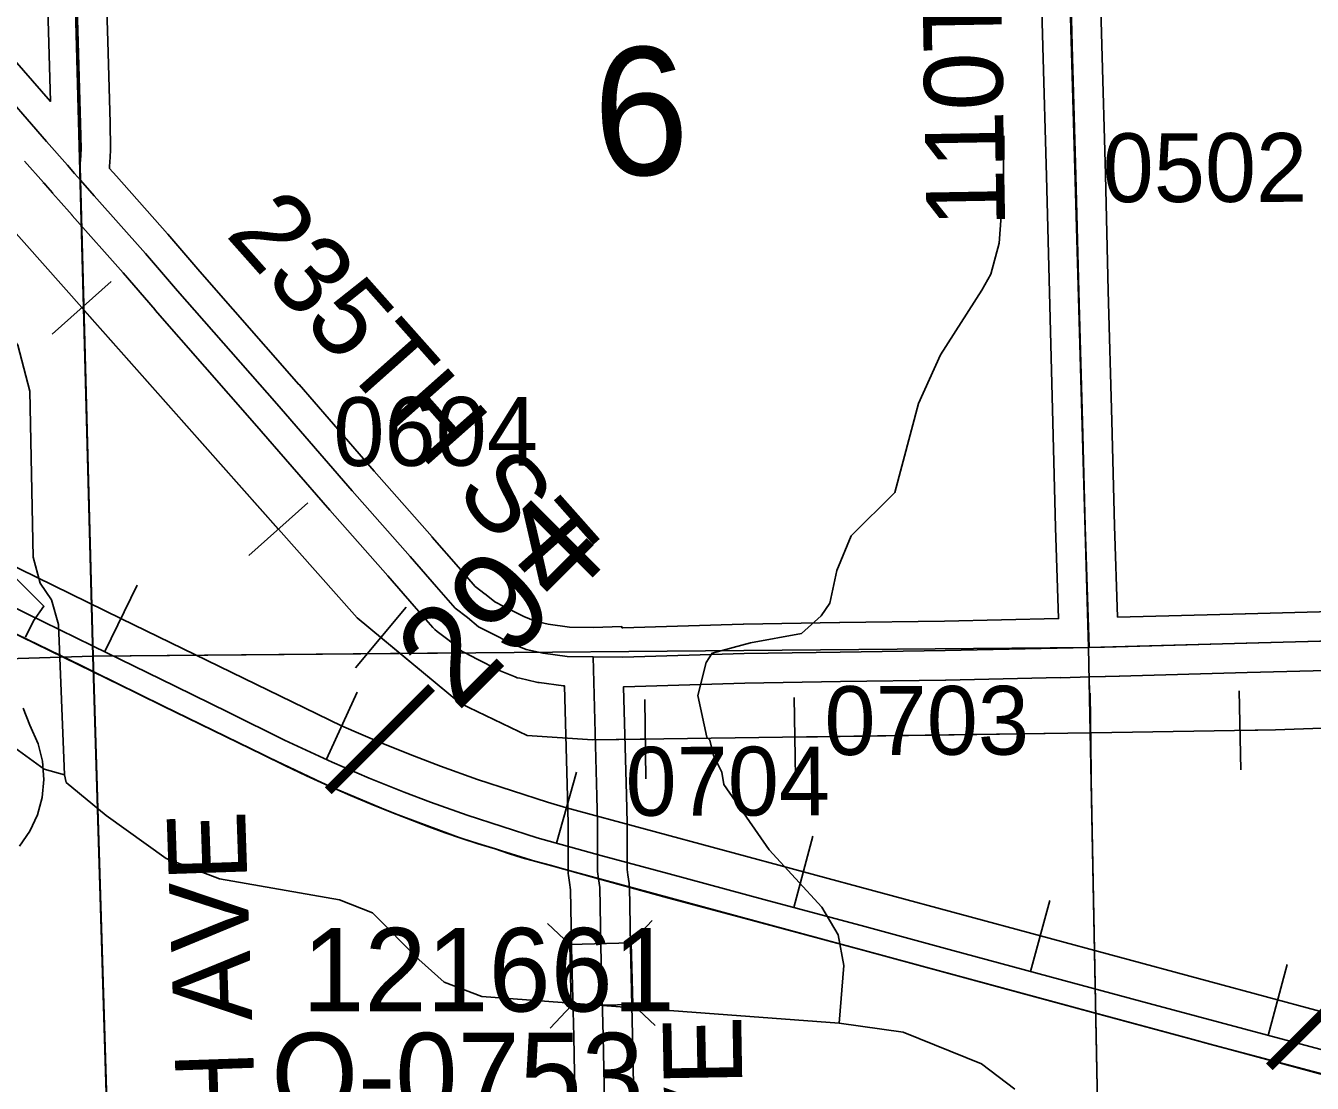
# Model space of a CAD drawing. Extents: x 128.7 to 185.5, y -21.4 to 12.6.
# Drawn here: x 134.119 to 135.429, y -9.118 to -8.042 of the extents above; entities that cross this region are included whole.
import ezdxf

# ---------------------------------------------------------------- set-up
doc = ezdxf.new("R2010")
doc.units = 0
for name, color, linetype in [('tdCoCoBndry', 7, 'Continuous'), ('tdCoCoBndryPart', 7, 'Continuous'), ('tdCoHydroRiver', 7, 'Continuous'), ('tdCoPipe', 7, 'Continuous'), ('tdCoPriCL', 7, 'Continuous'), ('tdCoPrimary', 7, 'Continuous'), ('tdCoPriNonDiv', 7, 'Continuous'), ('tdCoPriNonDivCL', 7, 'Continuous'), ('tdCoRRCL', 7, 'Continuous'), ('tdCoSecRdNmbr', 7, 'Continuous'), ('tdCoSecRdTxt', 7, 'Continuous'), ('tdCoSecRteBand', 7, 'Continuous'), ('tdCoSecRteCL', 7, 'Continuous'), ('tdCoSectLine', 7, 'Continuous'), ('tdCoSectLinePart', 7, 'Continuous'), ('tdCoSectNmbr', 7, 'Continuous'), ('tdCoShieldUsRte', 7, 'Continuous'), ('tdCoStrucSec', 7, 'Continuous'), ('tdCoStrucSecCoName', 7, 'Continuous'), ('tdCoStrucSecFHWANum', 7, 'Continuous'), ('tdCoSurfAsphalt', 7, 'Continuous'), ('tdCoSurfGravel', 7, 'Continuous'), ('tdCoTwpBndryShd', 7, 'Continuous'), ('tdStHwyPriRefPost1', 7, 'Continuous'), ('tdStHwyPriRefPost5', 7, 'Continuous')]:
    doc.layers.add(name, color=color, linetype=linetype)

msp = doc.modelspace()

# ---------------------------------------------------------------- linework, layer by layer
at = {"layer": 'tdCoCoBndry'}
for p, q in [((134.1615, -7.6994), (134.1879, -8.683)), ((134.1879, -8.683), (134.1615, -7.6994)), ((134.1879, -8.683), (134.219, -9.7062)), ((134.219, -9.7062), (134.1879, -8.683))]:
    msp.add_line(p, q, dxfattribs=at)
for points in [[(133.7886, 4.3475), (133.8188, 3.3421), (133.8473, 2.341), (133.878, 1.3376), (133.9067, 0.3357), (133.9391, -0.6703), (133.9673, -1.6731), (133.9961, -2.6778), (134.0303, -3.6816), (134.0608, -4.6883), (134.0947, -5.6895), (134.129, -6.6932), (134.1293, -6.7029), (134.1612, -7.6994), (134.1875, -8.683), (134.2186, -9.7062), (134.2417, -10.7094), (134.275, -11.7191), (134.2997, -12.7212), (134.329, -13.723)], [(133.8962, -2.6807), (134.0612, -7.7025), (134.1187, -9.7087), (134.1418, -10.7117), (134.1751, -11.7221), (134.2291, -13.7257), (134.2397, -13.7678), (134.2605, -13.7958), (134.2979, -13.818), (134.3318, -13.8228), (134.3294, -13.723), (134.3001, -12.7212), (134.2754, -11.7191), (134.2421, -10.7094), (134.219, -9.7062), (134.1879, -8.683), (134.1615, -7.6994), (134.1297, -6.7029)], [(140.1254, -13.5551), (139.3404, -13.58), (138.3387, -13.6015), (137.3418, -13.6288), (136.3432, -13.661), (135.3389, -13.6885), (134.3294, -13.723), (134.3001, -12.7212), (134.2754, -11.7191), (134.2421, -10.7094), (134.219, -9.7062), (134.1879, -8.683), (134.1615, -7.6994), (134.1297, -6.7029)]]:
    msp.add_lwpolyline(points, dxfattribs=at)
at = {"layer": 'tdCoCoBndryPart'}
msp.add_lwpolyline([(134.1758, -8.2449), (134.1875, -8.683), (134.2025, -9.1782)], dxfattribs=at)
at = {"layer": 'tdCoHydroRiver'}
for points in [[(135.1146, -8.1536), (135.1144, -8.2026), (135.1099, -8.2627), (135.1014, -8.2945), (135.0924, -8.3105), (135.0502, -8.3765), (135.028, -8.4261), (135.0038, -8.5167), (134.9594, -8.5606), (134.9446, -8.5958), (134.9377, -8.6291), (134.9287, -8.642), (134.9087, -8.66), (134.8569, -8.6694), (134.8177, -8.6801), (134.8117, -8.6897), (134.8032, -8.7231), (134.8124, -8.7654), (134.8156, -8.7685), (134.8193, -8.7842), (134.8277, -8.8013), (134.8296, -8.8138), (134.8758, -8.8803), (134.9296, -8.9387), (134.9462, -8.9666), (134.9518, -8.998), (134.9473, -9.0565)], [(134.1586, -8.8038), (134.1525, -8.6509), (134.1454, -8.6259), (134.1339, -8.6088), (134.1268, -8.5822), (134.1234, -8.4135), (134.1109, -8.3665), (134.1076, -8.3619), (134.1041, -8.3509), (134.0892, -8.3245), (134.0831, -8.3171)], [(134.0553, -8.7596), (134.1041, -8.7738), (134.1379, -8.7981), (134.1586, -8.8038), (134.1604, -8.8116), (134.2009, -8.8451), (134.2621, -8.8891), (134.3164, -8.9096), (134.4386, -8.9312), (134.4721, -8.9444), (134.5193, -8.9919), (134.5452, -9.0148), (134.5835, -9.0294), (134.9473, -9.0565), (135.0122, -9.0656), (135.0921, -9.098), (135.126, -9.1238)]]:
    msp.add_lwpolyline(points, dxfattribs=at)
at = {"layer": 'tdCoPipe'}
for p, q in [((134.146, -8.3554), (134.2062, -8.302)), ((134.3461, -8.5806), (134.4063, -8.527)), ((134.4548, -8.6951), (134.5062, -8.6331)), ((135.2037, -8.8016), (135.2026, -8.7209)), ((135.3559, -8.7989), (135.3545, -8.7184)), ((134.7505, -8.8079), (134.7493, -8.7273)), ((134.9026, -8.8058), (134.9014, -8.7253))]:
    msp.add_line(p, q, dxfattribs=at)
for points in [[(136.9009, -9.4255), (136.8169, -9.4094), (136.5505, -9.3406), (136.5159, -9.3231), (136.4089, -9.2225), (136.4044, -9.218), (135.9635, -8.7378), (135.3912, -8.758), (135.204, -8.7612), (134.6962, -8.7684), (134.6297, -8.7639), (134.5618, -8.7314), (134.4564, -8.6441), (134.037, -8.172)], [(134.3762, -8.5538), (134.1762, -8.3287)], [(134.7499, -8.7676), (134.6962, -8.7684), (134.6297, -8.7639), (134.5618, -8.7314), (134.4805, -8.6641)], [(135.2031, -8.7613), (134.902, -8.7655)], [(135.6562, -8.7486), (135.3912, -8.758), (135.3552, -8.7586)]]:
    msp.add_lwpolyline(points, dxfattribs=at)
at = {"layer": 'tdCoPriCL'}
msp.add_lwpolyline([(134.0884, -8.6507), (134.1751, -8.6926), (134.1883, -8.6991), (134.1994, -8.7045), (134.2023, -8.706), (134.205, -8.7073), (134.2584, -8.7336), (134.3608, -8.7836), (134.3828, -8.7945), (134.4049, -8.805), (134.4273, -8.8152), (134.4498, -8.8248), (134.4707, -8.8338), (134.4917, -8.8423), (134.5129, -8.8503), (134.5294, -8.8568), (134.5461, -8.8629), (134.5629, -8.8687), (134.5798, -8.8741), (134.5969, -8.8793), (134.6106, -8.8839), (134.6245, -8.8882), (134.6384, -8.8922), (134.6524, -8.8959), (134.702, -8.9096), (134.7724, -8.9291), (134.845, -8.9485), (134.9725, -8.9826), (135.13, -9.0254), (135.2167, -9.0488), (135.3035, -9.0723), (135.3283, -9.0791), (135.4689, -9.1164)], dxfattribs=at)
at = {"layer": 'tdCoPrimary'}
for points in [[(134.0884, -8.6505), (134.1754, -8.6926), (134.1883, -8.6989)], [(134.0884, -8.6505), (134.1754, -8.6926), (134.1883, -8.6989)], [(134.0884, -8.6505), (134.1754, -8.6926), (134.1883, -8.6989), (134.1883, -8.6989), (134.2588, -8.7336), (134.3612, -8.7836), (134.3832, -8.7945), (134.4053, -8.805), (134.4277, -8.8152), (134.4502, -8.8248), (134.471, -8.8338), (134.4921, -8.8423), (134.5133, -8.8503), (134.5298, -8.8568), (134.5465, -8.8629), (134.5633, -8.8687), (134.5802, -8.8741), (134.5972, -8.8793), (134.611, -8.8839), (134.6248, -8.8882), (134.6388, -8.8922), (134.6528, -8.8959), (134.7023, -8.9096), (134.7728, -8.9291), (134.8454, -8.9485), (134.9729, -8.9826), (135.1304, -9.0254), (135.3038, -9.0723), (135.3286, -9.0791), (135.4693, -9.1164)], [(134.1883, -8.6989), (134.1883, -8.6989), (134.2588, -8.7336), (134.3612, -8.7836), (134.3832, -8.7945), (134.4053, -8.805), (134.4277, -8.8152), (134.4502, -8.8248), (134.471, -8.8338), (134.4921, -8.8423), (134.5133, -8.8503), (134.5298, -8.8568), (134.5465, -8.8629), (134.5633, -8.8687), (134.5802, -8.8741), (134.5972, -8.8793), (134.611, -8.8839), (134.6248, -8.8882), (134.6388, -8.8922), (134.6528, -8.8959), (134.7023, -8.9096), (134.7728, -8.9291), (134.8454, -8.9485), (134.9729, -8.9826), (135.1304, -9.0254), (135.3038, -9.0723), (135.3286, -9.0791), (135.4693, -9.1164)], [(134.1883, -8.6989), (134.1883, -8.6989), (134.2588, -8.7336), (134.3612, -8.7836), (134.3832, -8.7945), (134.4053, -8.805), (134.4277, -8.8152), (134.4502, -8.8248), (134.471, -8.8338), (134.4921, -8.8423), (134.5133, -8.8503), (134.5298, -8.8568), (134.5465, -8.8629), (134.5633, -8.8687), (134.5802, -8.8741), (134.5972, -8.8793), (134.611, -8.8839), (134.6248, -8.8882), (134.6388, -8.8922), (134.6528, -8.8959), (134.7023, -8.9096), (134.7728, -8.9291), (134.8454, -8.9485), (134.9729, -8.9826), (135.1304, -9.0254), (135.3038, -9.0723), (135.3286, -9.0791), (135.4693, -9.1164)]]:
    msp.add_lwpolyline(points, dxfattribs=at)
at = {"layer": 'tdCoPriNonDiv'}
msp.add_lwpolyline([(134.0851, -8.6491), (134.3608, -8.7836), (134.4273, -8.8152), (134.4917, -8.8423), (134.5629, -8.8687), (134.6384, -8.8922), (135.3035, -9.0723), (136.2808, -9.3366)], dxfattribs=at)
at = {"layer": 'tdCoPriNonDivCL'}
for points in [[(134.0884, -8.6507), (134.1751, -8.6926)], [(134.0884, -8.6507), (134.1751, -8.6926), (134.1879, -8.6989)], [(134.1751, -8.6926), (134.1751, -8.6926), (134.188, -8.6989), (134.2584, -8.7336), (134.3608, -8.7836), (134.3828, -8.7945), (134.4049, -8.805), (134.4273, -8.8152), (134.4498, -8.8248), (134.4707, -8.8338), (134.4917, -8.8423), (134.5129, -8.8503), (134.5294, -8.8568), (134.5461, -8.8629), (134.5629, -8.8687), (134.5798, -8.8741), (134.5969, -8.8793), (134.6106, -8.8839), (134.6245, -8.8882), (134.6384, -8.8922), (134.6524, -8.8959), (134.702, -8.9096), (134.7724, -8.9291), (134.845, -8.9485), (134.9725, -8.9826), (135.13, -9.0254), (135.3035, -9.0723), (135.3283, -9.0791), (135.4689, -9.1164)], [(134.1879, -8.6989), (134.188, -8.6989), (134.2584, -8.7336), (134.3608, -8.7836), (134.3828, -8.7945), (134.4049, -8.805), (134.4273, -8.8152), (134.4498, -8.8248), (134.4707, -8.8338), (134.4917, -8.8423), (134.5129, -8.8503), (134.5294, -8.8568), (134.5461, -8.8629), (134.5629, -8.8687), (134.5798, -8.8741), (134.5969, -8.8793), (134.6106, -8.8839), (134.6245, -8.8882), (134.6384, -8.8922), (134.6524, -8.8959), (134.702, -8.9096), (134.7724, -8.9291), (134.845, -8.9485), (134.9725, -8.9826), (135.13, -9.0254), (135.3035, -9.0723), (135.3283, -9.0791), (135.4689, -9.1164)]]:
    msp.add_lwpolyline(points, dxfattribs=at)
at = {"layer": 'tdCoRRCL'}
for p, q in [((134.1996, -8.6783), (134.2326, -8.611)), ((134.4251, -8.7879), (134.4564, -8.7197)), ((134.6594, -8.8735), (134.6796, -8.8013)), ((134.9009, -8.9388), (134.9203, -8.8664)), ((135.142, -9.0041), (135.1615, -8.9316)), ((135.3839, -9.0693), (135.4033, -8.9968))]:
    msp.add_line(p, q, dxfattribs=at)
for points in [[(133.992, -8.5352), (134.2166, -8.645), (134.4406, -8.754), (134.4603, -8.7626), (134.4791, -8.7707), (134.4969, -8.7778), (134.5147, -8.7849), (134.5414, -8.7951), (134.5789, -8.8085), (134.6146, -8.82), (134.6502, -8.8316), (134.6697, -8.8374), (134.911, -8.9025), (135.152, -8.9678), (135.3934, -9.0327), (135.6349, -9.098)], [(135.481, -9.095), (135.3832, -9.0688), (135.2626, -9.0366), (135.1848, -9.0154), (135.0629, -8.9826), (134.9732, -8.9582), (134.8705, -8.9307), (134.774, -8.9047), (134.7045, -8.8861), (134.6398, -8.868), (134.5685, -8.845), (134.531, -8.8316), (134.5042, -8.8214), (134.4686, -8.8072), (134.4311, -8.791), (134.3826, -8.7687), (134.3257, -8.7406), (134.2712, -8.7136), (134.1872, -8.6725), (134.1205, -8.64), (134.0458, -8.6033), (133.9755, -8.5689)]]:
    msp.add_lwpolyline(points, dxfattribs=at)
at = {"layer": 'tdCoSecRteBand'}
for points in [[(134.1078, -8.0766), (134.1443, -8.1185), (134.1425, -8.0592), (134.1425, -8.0592), (134.1425, -8.0592), (134.1391, -7.9418), (134.1366, -7.8595), (134.1342, -7.7804), (134.132, -7.715), (134.13, -7.6516), (134.13, -7.6516), (134.13, -7.6516), (134.127, -7.5542), (134.1233, -7.4488), (134.1233, -7.4487), (134.1233, -7.4487), (134.1213, -7.3859), (134.1194, -7.3324), (134.1193, -7.3321), (134.1193, -7.3318), (134.1186, -7.2875)], [(134.7268, -8.6542), (134.8494, -8.6505), (134.8497, -8.6505), (134.8499, -8.6505), (134.9475, -8.649), (134.9476, -8.649), (134.9476, -8.649), (135.0545, -8.6475), (135.1705, -8.6449), (135.1675, -8.5523), (135.1675, -8.5522), (135.1675, -8.5521), (135.1648, -8.4453), (135.1611, -8.3132), (135.1611, -8.3131), (135.1611, -8.3131), (135.1582, -8.1948), (135.1545, -8.0629), (135.1545, -8.0628), (135.1545, -8.0628), (135.1508, -7.9265)], [(135.2107, -7.9248), (135.2144, -8.0612), (135.2181, -8.1931), (135.2181, -8.1932), (135.2181, -8.1932), (135.2211, -8.3115), (135.2248, -8.4437), (135.2248, -8.4437), (135.2248, -8.4437), (135.2275, -8.5504), (135.2305, -8.6435)], [(134.1991, -7.94), (134.2025, -8.0574), (134.205, -8.1405), (134.205, -8.1407), (134.205, -8.1408), (134.2055, -8.1662), (134.2055, -8.1674), (134.2054, -8.1686), (134.2047, -8.1809), (134.2047, -8.1811), (134.2047, -8.1813), (134.2045, -8.1833), (134.2043, -8.1867), (134.2043, -8.1867), (134.2114, -8.1948), (134.2634, -8.2534), (134.2636, -8.2536), (134.2638, -8.2538), (134.2962, -8.2917), (134.3972, -8.4067), (134.3972, -8.4068), (134.3973, -8.4068), (134.4739, -8.495), (134.5328, -8.5618), (134.5328, -8.5618), (134.5329, -8.5619), (134.5597, -8.5927), (134.5767, -8.6121), (134.5869, -8.6199), (134.5874, -8.6203), (134.5878, -8.6206), (134.5966, -8.6279), (134.6057, -8.6325), (134.6261, -8.6428), (134.6378, -8.6476), (134.651, -8.6507), (134.6725, -8.6535), (134.6966, -8.6538), (134.726, -8.653), (134.726, -8.6542), (134.7268, -8.6542)], [(134.6799, -9.2199), (134.6769, -9.0703), (134.6746, -8.98), (134.6746, -8.9798), (134.6746, -8.9796), (134.6743, -8.958), (134.6736, -8.9209), (134.6726, -8.9136), (134.6716, -8.9064), (134.6713, -8.9043), (134.6713, -8.9023), (134.6713, -8.8539), (134.6705, -8.8264), (134.6705, -8.8264), (134.6705, -8.8263), (134.6676, -8.7134), (134.6664, -8.7134), (134.6664, -8.7132), (134.6418, -8.71), (134.6403, -8.7098), (134.6389, -8.7095), (134.6219, -8.7055), (134.6195, -8.705), (134.6173, -8.7041), (134.6022, -8.6979), (134.6011, -8.6974), (134.6001, -8.6969), (134.5786, -8.6861), (134.5786, -8.686), (134.5785, -8.686), (134.5664, -8.6798), (134.5635, -8.6783), (134.561, -8.6762), (134.55, -8.6672), (134.5379, -8.658), (134.5355, -8.6561), (134.5336, -8.6539), (134.5146, -8.6322), (134.5146, -8.6322), (134.5145, -8.6321), (134.4877, -8.6014), (134.4288, -8.5346), (134.4288, -8.5345), (134.4287, -8.5344), (134.352, -8.4462), (134.251, -8.3311), (134.2509, -8.331), (134.2508, -8.3308), (134.2184, -8.2931), (134.1665, -8.2346), (134.1665, -8.2345), (134.1665, -8.2345), (134.1524, -8.2186), (134.1464, -8.2118), (134.1463, -8.2117), (134.1462, -8.2116), (134.1391, -8.2034), (134.1377, -8.2018), (134.137, -8.2016), (134.1371, -8.2012), (134.1178, -8.1794)], [(135.2305, -8.6435), (135.3607, -8.6399), (135.3607, -8.6399), (135.3608, -8.6399), (135.5621, -8.6345)], [(135.5638, -8.6945), (135.3624, -8.6999), (135.2322, -8.7034), (135.2322, -8.7035), (135.2181, -8.7038), (135.218, -8.7038), (135.218, -8.7038), (135.2023, -8.7042), (135.1725, -8.7052), (135.1725, -8.7049), (135.0557, -8.7075), (135.0556, -8.7075), (135.0554, -8.7075), (134.9484, -8.709), (134.851, -8.7105), (134.7279, -8.7142), (134.7276, -8.7142), (134.7305, -8.8247), (134.7313, -8.8526), (134.7314, -8.853), (134.7314, -8.8535), (134.7314, -8.9003), (134.7321, -8.9055), (134.7333, -8.9145), (134.7335, -8.9163), (134.7336, -8.918), (134.7343, -8.957), (134.7343, -8.9571), (134.7343, -8.9572), (134.7346, -8.9787), (134.7369, -9.0689), (134.7369, -9.069), (134.7369, -9.0691), (134.7399, -9.2186)]]:
    msp.add_lwpolyline(points, dxfattribs=at)
at = {"layer": 'tdCoSecRteCL'}
for points in [[(135.2015, -8.6742), (135.1975, -8.5513), (135.1948, -8.4445), (135.1911, -8.3123), (135.1882, -8.194), (135.1845, -8.062), (135.1808, -7.9256), (135.1766, -7.7851), (135.1726, -7.6675), (135.1716, -7.6398), (135.1677, -7.5138), (135.163, -7.3809), (135.1571, -7.2398), (135.1514, -7.0968), (135.1445, -6.9594), (135.1366, -6.807), (135.1299, -6.6764)], [(134.1744, -8.1817), (134.1746, -8.1812), (134.1747, -8.1792), (134.1755, -8.1668), (134.175, -8.1414), (134.1725, -8.0583), (134.1691, -7.9409), (134.1666, -7.8586), (134.1641, -7.7794), (134.162, -7.714), (134.1599, -7.6507), (134.157, -7.5533), (134.1533, -7.4477), (134.1513, -7.3848), (134.1493, -7.3313), (134.1486, -7.2867), (134.1451, -7.1989)], [(134.0721, -8.0815), (134.0852, -8.0963), (134.1402, -8.1594), (134.1617, -8.1836), (134.1689, -8.1919), (134.1749, -8.1988), (134.1889, -8.2147), (134.241, -8.2733), (134.2735, -8.3113), (134.3746, -8.4265), (134.4513, -8.5148), (134.5103, -8.5816), (134.5372, -8.6124), (134.5561, -8.6341), (134.5687, -8.6437), (134.5801, -8.6531), (134.5921, -8.6593), (134.6136, -8.6701), (134.6286, -8.6763), (134.6457, -8.6802), (134.6703, -8.6835), (134.6968, -8.6838)], [(135.2015, -8.6742), (135.2173, -8.6738), (135.3616, -8.6699), (135.563, -8.6645), (135.6772, -8.6605), (135.8671, -8.6563), (135.9514, -8.6534), (135.9734, -8.6551), (135.9819, -8.6584)], [(134.6968, -8.6838), (134.727, -8.6842), (134.8503, -8.6805), (134.948, -8.679), (135.055, -8.6775), (135.2015, -8.6742)], [(134.7166, -9.4408), (134.7141, -9.3606), (134.7099, -9.2193), (134.7069, -9.0697), (134.7046, -8.9793), (134.7043, -8.9576), (134.7036, -8.9186), (134.7023, -8.9096), (134.7013, -8.9023), (134.7013, -8.8535), (134.7005, -8.8255), (134.6968, -8.6838)]]:
    msp.add_lwpolyline(points, dxfattribs=at)
at = {"layer": 'tdCoSectLine'}
for points in [[(135.1725, -7.6763), (135.2011, -8.6742)], [(134.1612, -7.6994), (134.1875, -8.683)], [(135.2011, -8.6742), (136.2051, -8.6468)], [(134.0894, -8.6862), (134.1875, -8.683)], [(134.1875, -8.683), (135.2011, -8.6742)], [(134.1875, -8.683), (134.2186, -9.7062)], [(135.2011, -8.6742), (135.2206, -9.6734)]]:
    msp.add_lwpolyline(points, dxfattribs=at)
at = {"layer": 'tdCoSectLinePart'}
for points in [[(134.1758, -8.2449), (134.1875, -8.683)], [(134.0894, -8.6862), (134.1875, -8.683)], [(134.1875, -8.683), (134.5661, -8.6797)], [(134.1875, -8.683), (134.2025, -9.1782)], [(135.2017, -8.7041), (135.22, -9.6437)]]:
    msp.add_lwpolyline(points, dxfattribs=at)
at = {"layer": 'tdCoShieldUsRte'}
for points in [[(134.0587, -8.5535), (134.1376, -8.6324), (134.1269, -8.6473), (134.1189, -8.6639)], [(134.1164, -8.7362), (134.1234, -8.7532), (134.1318, -8.7723), (134.1362, -8.7901), (134.1375, -8.8085), (134.1358, -8.8268), (134.131, -8.8446), (134.1233, -8.8613), (134.1129, -8.8765)]]:
    msp.add_lwpolyline(points, dxfattribs=at)
at = {"layer": 'tdCoStrucSec'}
for p, q in [((134.6728, -8.9765), (134.6501, -8.955)), ((134.7354, -8.9749), (134.7569, -8.9522)), ((134.6744, -9.0391), (134.6529, -9.0618)), ((134.737, -9.0375), (134.7597, -9.059))]:
    msp.add_line(p, q, dxfattribs=at)
msp.add_lwpolyline([(134.6744, -9.0391), (134.6728, -8.9765), (134.7354, -8.9749), (134.737, -9.0375)], close=True, dxfattribs=at)
at = {"layer": 'tdCoSurfAsphalt'}
msp.add_lwpolyline([(134.0852, -8.0963), (134.1402, -8.1594), (134.1617, -8.1836), (134.1689, -8.1919), (134.1749, -8.1988), (134.1889, -8.2147), (134.241, -8.2733), (134.2735, -8.3113), (134.3746, -8.4265), (134.4513, -8.5148), (134.5103, -8.5816), (134.5372, -8.6124), (134.5561, -8.6341), (134.5687, -8.6437), (134.5801, -8.6531), (134.5921, -8.6593), (134.6136, -8.6701), (134.6286, -8.6763), (134.6457, -8.6802), (134.6703, -8.6835), (134.6968, -8.6838), (134.727, -8.6842), (134.8503, -8.6805), (134.948, -8.679), (135.055, -8.6775), (135.2015, -8.6742), (135.2173, -8.6738), (135.3616, -8.6699), (135.563, -8.6645)], dxfattribs=at)
at = {"layer": 'tdCoSurfGravel'}
for points in [[(135.2015, -8.6742), (135.1975, -8.5513), (135.1948, -8.4445), (135.1911, -8.3123), (135.1882, -8.194), (135.1845, -8.062), (135.1808, -7.9256), (135.1766, -7.7851), (135.1726, -7.6675)], [(134.1744, -8.1817), (134.1746, -8.1812), (134.1747, -8.1792), (134.1755, -8.1668), (134.175, -8.1414), (134.1725, -8.0583), (134.1691, -7.9409), (134.1666, -7.8586), (134.1641, -7.7794), (134.162, -7.714)], [(134.7412, -10.4728), (134.7392, -10.3584), (134.7373, -10.2462), (134.7338, -10.1158), (134.7289, -9.9745), (134.7257, -9.8534), (134.7239, -9.7426), (134.7228, -9.6913), (134.7215, -9.6317), (134.7175, -9.4899), (134.7166, -9.4408), (134.7141, -9.3606), (134.7099, -9.2193), (134.7069, -9.0697), (134.7046, -8.9793), (134.7043, -8.9576), (134.7036, -8.9186), (134.7023, -8.9096), (134.7013, -8.9023), (134.7013, -8.8535), (134.7005, -8.8255), (134.6968, -8.6838)]]:
    msp.add_lwpolyline(points, dxfattribs=at)
at = {"layer": 'tdCoTwpBndryShd'}
msp.add_lwpolyline([(134.1293, -6.7029), (134.1612, -7.6994), (134.1875, -8.683), (134.2186, -9.7062), (134.2417, -10.7094), (134.275, -11.7191), (134.2997, -12.7212), (134.329, -13.723), (135.3385, -13.6885), (136.3429, -13.661), (137.3414, -13.6288), (138.3383, -13.6015), (139.34, -13.58), (139.5652, -13.5728)], dxfattribs=at)

# ---------------------------------------------------------------- texts
at = {"layer": 'tdCoSecRdNmbr'}
for s, rotation, p in [('0502', 0.1028, (135.2154, -8.2211)), ('0604', 0.1022, (134.4323, -8.4896)), ('0703', 0.1026, (134.9322, -8.7837)), ('0704', 0.1024, (134.7297, -8.8455))]:
    msp.add_text(s, height=0.07, rotation=rotation, dxfattribs=at).set_placement(p)
at = {"layer": 'tdCoSecRdTxt'}
for s, rotation, p in [('110TH AVE', 91, (135.1162, -8.2463)), ('235TH ST', 311.6217, (134.3215, -8.2544)), ('100TH AVE', 91.943, (134.3615, -9.4042)), ('105TH AVE', 91, (134.8572, -9.6135))]:
    msp.add_text(s, height=0.08, rotation=rotation, dxfattribs=at).set_placement(p)
at = {"layer": 'tdCoSectNmbr'}
msp.add_text('6', height=0.13, rotation=2.6547, dxfattribs=at).set_placement((134.6997, -8.1957))
at = {"layer": 'tdCoStrucSecCoName'}
msp.add_text('Q-0753', height=0.085, dxfattribs=at).set_placement((134.3691, -9.1514))
at = {"layer": 'tdCoStrucSecFHWANum'}
msp.add_text('121661', height=0.085, dxfattribs=at).set_placement((134.4006, -9.0447))
at = {"layer": 'tdStHwyPriRefPost1'}
for s, p in [('‒‒294', (134.4531, -8.8462)), ('‒‒295', (135.4111, -9.1271))]:
    msp.add_text(s, height=0.1, rotation=45, dxfattribs=at).set_placement(p)
at = {"layer": 'tdStHwyPriRefPost5'}
msp.add_text('‒‒295', height=0.1, rotation=45, dxfattribs=at).set_placement((135.4111, -9.1271))

doc.saveas('drawing.dxf')
